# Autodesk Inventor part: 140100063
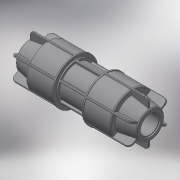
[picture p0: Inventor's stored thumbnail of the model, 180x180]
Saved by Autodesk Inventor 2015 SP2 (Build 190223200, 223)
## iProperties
Created: 2018-02
Part Number: 140100063
Material: Generic
Description: PLASSON L.14 COUPLER (SILVER) 63
Document SubType Name: Modeling
Designer: KIM
Mass: 640.444 g
Surface Area: 1063.83 cm^2
Volume: 640.444 cm^3
Density: 1 g/cm^3
Appearance: Default
Author: KIM
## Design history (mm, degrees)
derived "140100.ipt"
feature "Solid1::140100.ipt"
tag "TaggingFeature1"
body "Solid1"
other parameters: "d30" = 1, "d36" = 1.67, "d65" = 102.82, "d77" = 57.96, "d93" = 81.9, "d95" = 25.05, "d96" = 1.67, "d97" = 69.3, "d100" = 79.5, "d102" = 63.46, "d103" = 1.67, "d107" = 62.65, "d113" = 106, "d114" = 6.3, "d115" = 3.15, "d117" = 0, "d126" = 10.6, "d127" = 1.06, "d129" = 360 deg, "d131" = 1.67, "d132" = 106, "d138" = 100 deg, "d139" = 90.1, "d141" = 167, "d142" = 63, "d143" = 82, "d144" = 0, "d145" = 63, "d146" = 82, "d147" = 0, "d149" = 5.3, "d150" = 2.65, "d152" = 0, "d153" = 1.06, "d155" = 360 deg, "E_" = 106, "l_" = 82, "d_" = 63, "H_" = 167
